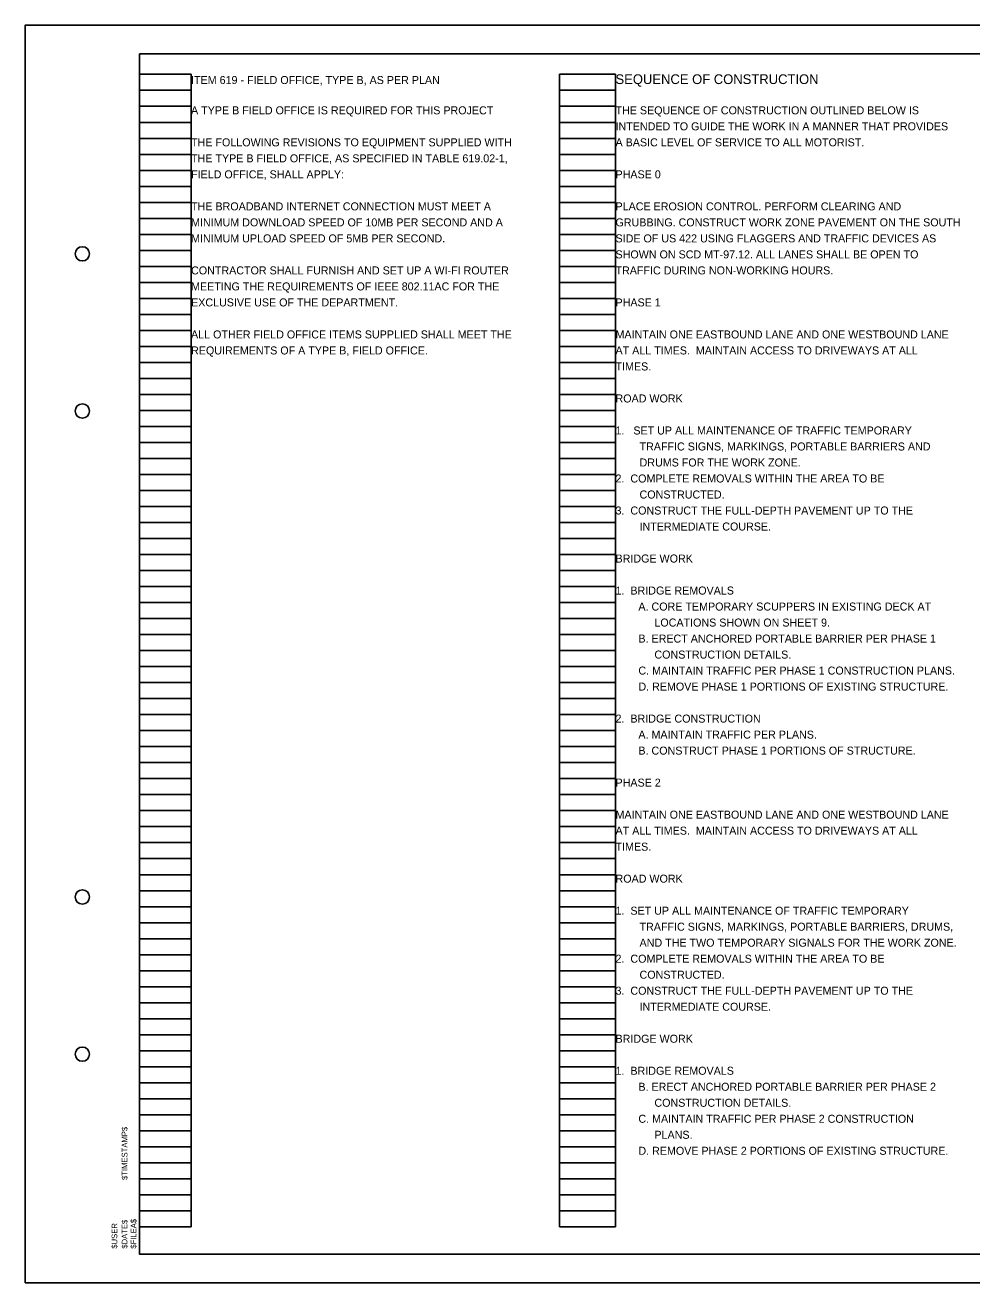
# Model space of a CAD drawing. Extents: x 0 to 34, y 0 to 22.
# Drawn here: x 0 to 16.55, y 0 to 22 of the extents above; entities that cross this region are included whole.
import ezdxf

# ---------------------------------------------------------------- set-up
doc = ezdxf.new("R2010")
doc.units = 0
for name, color, linetype in [('SC_Scratch1', 7, 'Continuous'), ('SH_Border', 7, 'Continuous'), ('SH_Cut_Line', 7, 'Continuous'), ('SH_Data', 7, 'Continuous'), ('SH_Text', 7, 'Continuous')]:
    doc.layers.add(name, color=color, linetype=linetype)

msp = doc.modelspace()

# ---------------------------------------------------------------- linework, layer by layer
at = {"layer": 'SC_Scratch1'}
for p, q in [((2, 0.98), (2, 21.14)), ((2, 21.14), (2.9, 21.14)), ((2.9, 0.98), (2.9, 21.14)), ((9.34, 0.98), (9.34, 21.14)), ((9.34, 21.14), (10.32, 21.14)), ((10.32, 0.98), (10.32, 21.14)), ((2, 20.86), (2.9, 20.86)), ((9.34, 20.86), (10.32, 20.86)), ((2, 20.58), (2.9, 20.58)), ((9.34, 20.58), (10.32, 20.58)), ((2, 20.3), (2.9, 20.3)), ((9.34, 20.3), (10.32, 20.3)), ((2, 20.02), (2.9, 20.02)), ((9.34, 20.02), (10.32, 20.02)), ((2, 19.74), (2.9, 19.74)), ((9.34, 19.74), (10.32, 19.74)), ((2, 19.46), (2.9, 19.46)), ((9.34, 19.46), (10.32, 19.46)), ((2, 19.18), (2.9, 19.18)), ((9.34, 19.18), (10.32, 19.18)), ((2, 18.9), (2.9, 18.9)), ((9.34, 18.9), (10.32, 18.9)), ((2, 18.62), (2.9, 18.62)), ((9.34, 18.62), (10.32, 18.62)), ((2, 18.34), (2.9, 18.34)), ((9.34, 18.34), (10.32, 18.34)), ((2, 18.06), (2.9, 18.06)), ((9.34, 18.06), (10.32, 18.06)), ((2, 17.78), (2.9, 17.78)), ((9.34, 17.78), (10.32, 17.78)), ((2, 17.5), (2.9, 17.5)), ((9.34, 17.5), (10.32, 17.5)), ((2, 17.22), (2.9, 17.22)), ((9.34, 17.22), (10.32, 17.22)), ((2, 16.94), (2.9, 16.94)), ((9.34, 16.94), (10.32, 16.94)), ((2, 16.66), (2.9, 16.66)), ((9.34, 16.66), (10.32, 16.66)), ((2, 16.38), (2.9, 16.38)), ((9.34, 16.38), (10.32, 16.38)), ((2, 16.1), (2.9, 16.1)), ((9.34, 16.1), (10.32, 16.1)), ((2, 15.82), (2.9, 15.82)), ((9.34, 15.82), (10.32, 15.82)), ((2, 15.54), (2.9, 15.54)), ((9.34, 15.54), (10.32, 15.54)), ((2, 15.26), (2.9, 15.26)), ((9.34, 15.26), (10.32, 15.26)), ((2, 14.98), (2.9, 14.98)), ((9.34, 14.98), (10.32, 14.98)), ((2, 14.7), (2.9, 14.7)), ((9.34, 14.7), (10.32, 14.7)), ((2, 14.42), (2.9, 14.42)), ((9.34, 14.42), (10.32, 14.42)), ((2, 14.14), (2.9, 14.14)), ((9.34, 14.14), (10.32, 14.14)), ((2, 13.86), (2.9, 13.86)), ((9.34, 13.86), (10.32, 13.86)), ((2, 13.58), (2.9, 13.58)), ((9.34, 13.58), (10.32, 13.58)), ((2, 13.3), (2.9, 13.3)), ((9.34, 13.3), (10.32, 13.3)), ((2, 13.02), (2.9, 13.02)), ((9.34, 13.02), (10.32, 13.02)), ((2, 12.74), (2.9, 12.74)), ((9.34, 12.74), (10.32, 12.74)), ((2, 12.46), (2.9, 12.46)), ((9.34, 12.46), (10.32, 12.46)), ((2, 12.18), (2.9, 12.18)), ((9.34, 12.18), (10.32, 12.18)), ((2, 11.9), (2.9, 11.9)), ((9.34, 11.9), (10.32, 11.9)), ((2, 11.62), (2.9, 11.62)), ((9.34, 11.62), (10.32, 11.62)), ((2, 11.34), (2.9, 11.34)), ((9.34, 11.34), (10.32, 11.34)), ((2, 11.06), (2.9, 11.06)), ((9.34, 11.06), (10.32, 11.06)), ((2, 10.78), (2.9, 10.78)), ((9.34, 10.78), (10.32, 10.78)), ((2, 10.5), (2.9, 10.5)), ((9.34, 10.5), (10.32, 10.5)), ((2, 10.22), (2.9, 10.22)), ((9.34, 10.22), (10.32, 10.22)), ((2, 9.94), (2.9, 9.94)), ((9.34, 9.94), (10.32, 9.94)), ((2, 9.66), (2.9, 9.66)), ((9.34, 9.66), (10.32, 9.66)), ((2, 9.38), (2.9, 9.38)), ((9.34, 9.38), (10.32, 9.38)), ((2, 9.1), (2.9, 9.1)), ((9.34, 9.1), (10.32, 9.1)), ((2, 8.82), (2.9, 8.82)), ((9.34, 8.82), (10.32, 8.82)), ((2, 8.54), (2.9, 8.54)), ((9.34, 8.54), (10.32, 8.54)), ((2, 8.26), (2.9, 8.26)), ((9.34, 8.26), (10.32, 8.26)), ((2, 7.98), (2.9, 7.98)), ((9.34, 7.98), (10.32, 7.98)), ((2, 7.7), (2.9, 7.7)), ((9.34, 7.7), (10.32, 7.7)), ((2, 7.42), (2.9, 7.42)), ((9.34, 7.42), (10.32, 7.42)), ((2, 7.14), (2.9, 7.14)), ((9.34, 7.14), (10.32, 7.14)), ((2, 6.86), (2.9, 6.86)), ((9.34, 6.86), (10.32, 6.86)), ((2, 6.58), (2.9, 6.58)), ((9.34, 6.58), (10.32, 6.58)), ((2, 6.3), (2.9, 6.3)), ((9.34, 6.3), (10.32, 6.3)), ((2, 6.02), (2.9, 6.02)), ((9.34, 6.02), (10.32, 6.02)), ((2, 5.74), (2.9, 5.74)), ((9.34, 5.74), (10.32, 5.74)), ((2, 5.46), (2.9, 5.46)), ((9.34, 5.46), (10.32, 5.46)), ((2, 5.18), (2.9, 5.18)), ((9.34, 5.18), (10.32, 5.18)), ((2, 4.9), (2.9, 4.9)), ((9.34, 4.9), (10.32, 4.9)), ((2, 4.62), (2.9, 4.62)), ((9.34, 4.62), (10.32, 4.62)), ((2, 4.34), (2.9, 4.34)), ((9.34, 4.34), (10.32, 4.34)), ((2, 4.06), (2.9, 4.06)), ((9.34, 4.06), (10.32, 4.06)), ((2, 3.78), (2.9, 3.78)), ((9.34, 3.78), (10.32, 3.78)), ((2, 3.5), (2.9, 3.5)), ((9.34, 3.5), (10.32, 3.5)), ((2, 3.22), (2.9, 3.22)), ((9.34, 3.22), (10.32, 3.22)), ((2, 2.94), (2.9, 2.94)), ((9.34, 2.94), (10.32, 2.94)), ((2, 2.66), (2.9, 2.66)), ((9.34, 2.66), (10.32, 2.66)), ((2, 2.38), (2.9, 2.38)), ((9.34, 2.38), (10.32, 2.38)), ((2, 2.1), (2.9, 2.1)), ((9.34, 2.1), (10.32, 2.1)), ((2, 1.82), (2.9, 1.82)), ((9.34, 1.82), (10.32, 1.82)), ((2, 1.54), (2.9, 1.54)), ((9.34, 1.54), (10.32, 1.54)), ((2, 1.26), (2.9, 1.26)), ((9.34, 1.26), (10.32, 1.26)), ((2, 0.98), (2.9, 0.98)), ((9.34, 0.98), (10.32, 0.98)), ((0, 0), (0, 0))]:
    msp.add_line(p, q, dxfattribs=at)
at = {"layer": 'SH_Border'}
msp.add_lwpolyline([(2, 21.5), (33.5, 21.5), (33.5, 0.5), (2, 0.5)], close=True, dxfattribs=at)
for centre in [(1, 18), (1, 15.25), (1, 6.75), (1, 4)]:
    msp.add_circle(centre, 0.125, dxfattribs=at)
at = {"layer": 'SH_Cut_Line'}
msp.add_lwpolyline([(0, 0), (34, 0), (34, 22), (0, 22)], close=True, dxfattribs=at)

# ---------------------------------------------------------------- texts
at = {"layer": 'SH_Data'}
for s, p in [('$TIMESTAMP$', (1.788, 1.8)), ('$DATE$', (1.788, 0.598)), ('$FILEA$', (1.944, 0.598)), ('$USER', (1.611, 0.598))]:
    msp.add_text(s, height=0.1, rotation=89.9931, dxfattribs=at).set_placement(p)
at = {"layer": 'SH_Text'}
for s, height, p in [('SEQUENCE OF CONSTRUCTION', 0.17, (10.32, 20.97)), ('ITEM 619 - FIELD OFFICE, TYPE B, AS PER PLAN', 0.14, (2.9, 20.97)), ('A TYPE B FIELD OFFICE IS REQUIRED FOR THIS PROJECT', 0.14, (2.9, 20.44)), ('THE SEQUENCE OF CONSTRUCTION OUTLINED BELOW IS ', 0.14, (10.32, 20.44)), ('INTENDED TO GUIDE THE WORK IN A MANNER THAT PROVIDES ', 0.14, (10.32, 20.16)), ('THE FOLLOWING REVISIONS TO EQUIPMENT SUPPLIED WITH ', 0.14, (2.9, 19.88)), ('A BASIC LEVEL OF SERVICE TO ALL MOTORIST.', 0.14, (10.32, 19.88)), ('THE TYPE B FIELD OFFICE, AS SPECIFIED IN TABLE 619.02-1, ', 0.14, (2.9, 19.6)), ('FIELD OFFICE, SHALL APPLY:', 0.14, (2.9, 19.32)), ('PHASE 0', 0.14, (10.32, 19.32)), ('THE BROADBAND INTERNET CONNECTION MUST MEET A ', 0.14, (2.9, 18.76)), ('PLACE EROSION CONTROL. PERFORM CLEARING AND ', 0.14, (10.32, 18.76)), ('MINIMUM DOWNLOAD SPEED OF 10MB PER SECOND AND A ', 0.14, (2.9, 18.48)), ('GRUBBING. CONSTRUCT WORK ZONE PAVEMENT ON THE SOUTH ', 0.14, (10.32, 18.48)), ('MINIMUM UPLOAD SPEED OF 5MB PER SECOND.', 0.14, (2.9, 18.2)), ('SIDE OF US 422 USING FLAGGERS AND TRAFFIC DEVICES AS ', 0.14, (10.32, 18.2)), ('SHOWN ON SCD MT-97.12. ALL LANES SHALL BE OPEN TO ', 0.14, (10.32, 17.92)), ('CONTRACTOR SHALL FURNISH AND SET UP A WI-FI ROUTER ', 0.14, (2.9, 17.64)), ('TRAFFIC DURING NON-WORKING HOURS. ', 0.14, (10.32, 17.64)), ('MEETING THE REQUIREMENTS OF IEEE 802.11AC FOR THE ', 0.14, (2.9, 17.36)), ('EXCLUSIVE USE OF THE DEPARTMENT. ', 0.14, (2.9, 17.08)), ('PHASE 1', 0.14, (10.32, 17.08)), ('ALL OTHER FIELD OFFICE ITEMS SUPPLIED SHALL MEET THE ', 0.14, (2.9, 16.52)), ('MAINTAIN ONE EASTBOUND LANE AND ONE WESTBOUND LANE ', 0.14, (10.32, 16.52)), ('REQUIREMENTS OF A TYPE B, FIELD OFFICE.', 0.14, (2.9, 16.24)), ('AT ALL TIMES.  MAINTAIN ACCESS TO DRIVEWAYS AT ALL ', 0.14, (10.32, 16.24)), ('TIMES.', 0.14, (10.32, 15.96)), ('ROAD WORK', 0.14, (10.32, 15.4)), ('1.   SET UP ALL MAINTENANCE OF TRAFFIC TEMPORARY ', 0.14, (10.32, 14.84)), ('TRAFFIC SIGNS, MARKINGS, PORTABLE BARRIERS AND ', 0.14, (10.74, 14.56)), ('DRUMS FOR THE WORK ZONE.', 0.14, (10.74, 14.28)), ('2.  COMPLETE REMOVALS WITHIN THE AREA TO BE ', 0.14, (10.32, 14)), ('CONSTRUCTED.', 0.14, (10.74, 13.72)), ('3.  CONSTRUCT THE FULL-DEPTH PAVEMENT UP TO THE ', 0.14, (10.32, 13.44)), ('INTERMEDIATE COURSE.', 0.14, (10.74, 13.16)), ('BRIDGE WORK', 0.14, (10.32, 12.6)), ('1.  BRIDGE REMOVALS', 0.14, (10.32, 12.04)), ('A. CORE TEMPORARY SCUPPERS IN EXISTING DECK AT ', 0.14, (10.72, 11.76)), ('LOCATIONS SHOWN ON SHEET 9.', 0.14, (11, 11.48)), ('B. ERECT ANCHORED PORTABLE BARRIER PER PHASE 1 ', 0.14, (10.72, 11.2)), ('CONSTRUCTION DETAILS.', 0.14, (11, 10.92)), ('C. MAINTAIN TRAFFIC PER PHASE 1 CONSTRUCTION PLANS.', 0.14, (10.72, 10.64)), ('D. REMOVE PHASE 1 PORTIONS OF EXISTING STRUCTURE.', 0.14, (10.72, 10.36)), ('2.  BRIDGE CONSTRUCTION', 0.14, (10.32, 9.8)), ('A. MAINTAIN TRAFFIC PER PLANS.', 0.14, (10.72, 9.52)), ('B. CONSTRUCT PHASE 1 PORTIONS OF STRUCTURE.', 0.14, (10.72, 9.24)), ('PHASE 2', 0.14, (10.32, 8.68)), ('MAINTAIN ONE EASTBOUND LANE AND ONE WESTBOUND LANE ', 0.14, (10.32, 8.12)), ('AT ALL TIMES.  MAINTAIN ACCESS TO DRIVEWAYS AT ALL ', 0.14, (10.32, 7.84)), ('TIMES.', 0.14, (10.32, 7.56)), ('ROAD WORK', 0.14, (10.32, 7)), ('1.  SET UP ALL MAINTENANCE OF TRAFFIC TEMPORARY ', 0.14, (10.32, 6.44)), ('TRAFFIC SIGNS, MARKINGS, PORTABLE BARRIERS, DRUMS, ', 0.14, (10.74, 6.16)), ('AND THE TWO TEMPORARY SIGNALS FOR THE WORK ZONE.', 0.14, (10.74, 5.88)), ('2.  COMPLETE REMOVALS WITHIN THE AREA TO BE ', 0.14, (10.32, 5.6)), ('CONSTRUCTED.', 0.14, (10.74, 5.32)), ('3.  CONSTRUCT THE FULL-DEPTH PAVEMENT UP TO THE ', 0.14, (10.32, 5.04)), ('INTERMEDIATE COURSE.', 0.14, (10.74, 4.76)), ('BRIDGE WORK', 0.14, (10.32, 4.2)), ('1.  BRIDGE REMOVALS', 0.14, (10.32, 3.64)), ('B. ERECT ANCHORED PORTABLE BARRIER PER PHASE 2 ', 0.14, (10.72, 3.36)), ('CONSTRUCTION DETAILS.', 0.14, (11, 3.08)), ('C. MAINTAIN TRAFFIC PER PHASE 2 CONSTRUCTION ', 0.14, (10.72, 2.8)), ('PLANS.', 0.14, (11, 2.52)), ('D. REMOVE PHASE 2 PORTIONS OF EXISTING STRUCTURE.', 0.14, (10.72, 2.24))]:
    msp.add_text(s, height=height, dxfattribs=at).set_placement(p)

doc.saveas('drawing.dxf')
